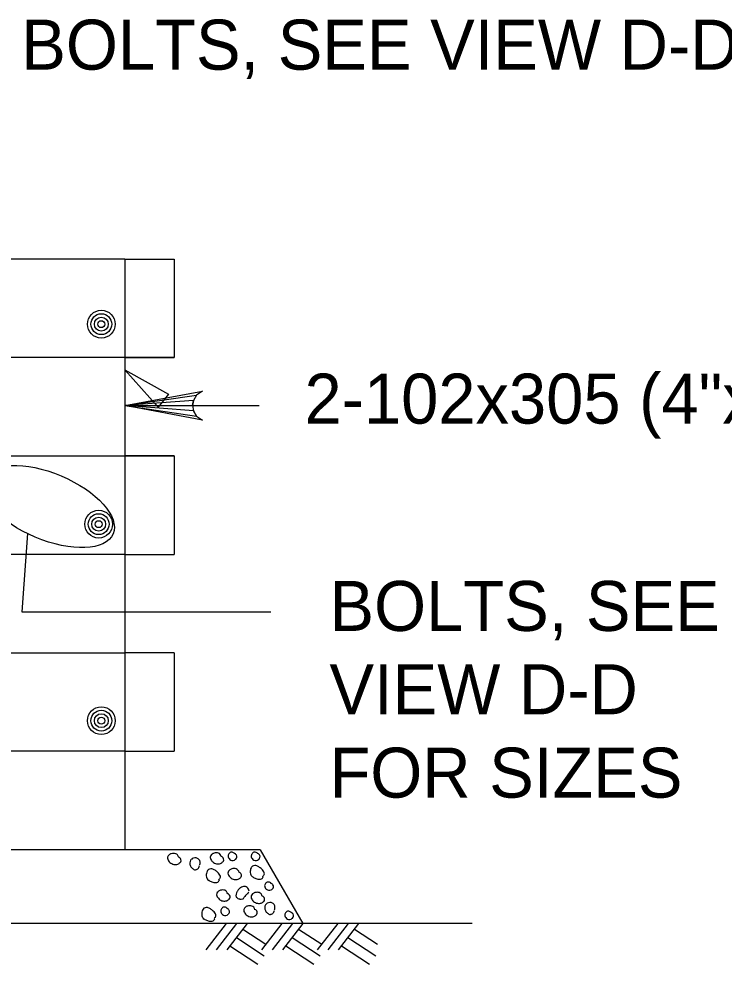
# Model space of a CAD drawing. Extents: x 0 to 36.3, y -44 to 0.
# Drawn here: x 21.652 to 23.344, y -17.273 to -15.005 of the extents above; entities that cross this region are included whole.
import ezdxf

# ---------------------------------------------------------------- set-up
doc = ezdxf.new("R2010")
doc.units = 0
doc.layers.add('3', color=7, linetype='Continuous')
doc.layers.add('5', color=7, linetype='Continuous')

msp = doc.modelspace()

# ---------------------------------------------------------------- linework, layer by layer
at = {"layer": '3'}
for p, q in [((21.9062, -15.5814), (21.5518, -15.5814)), ((21.9062, -15.5814), (21.9062, -16.9987)), ((21.9062, -15.5814), (22.0242, -15.5814)), ((22.0242, -15.5814), (22.0242, -15.8176)), ((21.9062, -15.8176), (21.5518, -15.8176)), ((22.0242, -15.8176), (21.8766, -15.8176)), ((21.9062, -15.8176), (22.0242, -15.8176)), ((21.5518, -16.0538), (21.9062, -16.0538)), ((21.8766, -16.0538), (22.0242, -16.0538)), ((22.0242, -16.0538), (21.9062, -16.0538)), ((22.0242, -16.0538), (22.0242, -16.29)), ((21.9062, -16.29), (21.5518, -16.29)), ((21.9062, -16.29), (22.0242, -16.29)), ((21.5518, -16.5263), (21.9062, -16.5263)), ((22.0242, -16.5263), (21.9062, -16.5263)), ((22.0242, -16.5263), (22.0242, -16.7625)), ((21.9062, -16.7625), (21.5518, -16.7625)), ((21.9062, -16.7625), (22.0242, -16.7625)), ((22.2309, -16.9987), (18.2742, -16.9987)), ((22.2309, -16.9987), (22.3332, -17.1758)), ((22.7392, -17.1758), (17.728, -17.1758)), ((22.149, -17.1758), (22.1002, -17.2395)), ((22.1742, -17.1758), (22.1253, -17.2395)), ((22.1993, -17.1758), (22.1505, -17.2395)), ((22.1891, -17.1892), (22.2446, -17.2257)), ((22.2828, -17.1758), (22.234, -17.2395)), ((22.308, -17.1758), (22.2592, -17.2395)), ((22.3332, -17.1758), (22.2844, -17.2395)), ((22.323, -17.1892), (22.3785, -17.2257)), ((22.4168, -17.1758), (22.3679, -17.2395)), ((22.4419, -17.1758), (22.3931, -17.2395)), ((22.4671, -17.1758), (22.4183, -17.2395)), ((22.4568, -17.1892), (22.5123, -17.2257)), ((22.1737, -17.2093), (22.2407, -17.2532)), ((22.3076, -17.2093), (22.3746, -17.2532)), ((22.4415, -17.2093), (22.5084, -17.2532)), ((22.1583, -17.2293), (22.2253, -17.2733)), ((22.2922, -17.2293), (22.3592, -17.2733)), ((22.4261, -17.2293), (22.4931, -17.2733))]:
    msp.add_line(p, q, dxfattribs=at)
for centre, radius in [((21.8496, -15.7374), 0.0333), ((21.8496, -15.7374), 0.025), ((21.8496, -15.7374), 0.0167), ((21.8496, -15.7374), 0.00833), ((21.8433, -16.2174), 0.0333), ((21.8433, -16.2174), 0.025), ((21.8433, -16.2174), 0.0167), ((21.8433, -16.2174), 0.00833), ((21.8496, -16.6891), 0.0333), ((21.8496, -16.6891), 0.025), ((21.8496, -16.6891), 0.0167), ((21.8496, -16.6891), 0.00833)]:
    msp.add_circle(centre, radius, dxfattribs=at)
for centre, radius, start, end in [((22.0196, -17.0202), 0.0115, 132.2712, 160.92), ((22.0221, -17.0229), 0.0153, 107.4489, 132.2712), ((22.023, -17.0257), 0.0182, 90, 107.449), ((22.023, -17.023), 0.0155, 71.0851, 90), ((22.0248, -17.0176), 0.00984, 39.2919, 71.0851), ((22.0216, -17.0203), 0.014, 12.7289, 39.2919), ((22.1221, -17.0187), 0.0115, 132.2712, 160.92), ((22.1246, -17.0215), 0.0153, 107.4489, 132.2712), ((22.1255, -17.0242), 0.0182, 90, 107.449), ((22.1255, -17.0215), 0.0155, 71.0851, 90), ((22.1273, -17.0162), 0.00984, 39.2919, 71.0851), ((22.1241, -17.0188), 0.014, 12.7289, 39.2919), ((22.1623, -17.0138), 0.00848, 153.4329, 176.3744), ((22.1635, -17.0139), 0.00973, 176.3744, 204.4459), ((22.1651, -17.0152), 0.0116, 133.8613, 153.4329), ((22.1625, -17.0126), 0.00794, 82.8756, 133.8613), ((22.1623, -17.014), 0.00935, 36.1405, 82.8756), ((22.1664, -17.0162), 0.00871, 33.6924, 77.7435), ((22.1674, -17.0155), 0.0075, 345.9971, 33.6924), ((22.2178, -17.0138), 0.00848, 153.4329, 176.3744), ((22.219, -17.0139), 0.00973, 176.3744, 204.4459), ((22.2206, -17.0152), 0.0116, 133.8613, 153.4329), ((22.218, -17.0126), 0.00794, 82.8756, 133.8613), ((22.2179, -17.014), 0.00935, 36.1405, 82.8756), ((22.222, -17.0162), 0.00871, 33.6924, 77.7435), ((22.223, -17.0155), 0.0075, 345.9971, 33.6924), ((22.0157, -17.0188), 0.00738, 160.92, 203.6312), ((22.0289, -17.013), 0.0219, 203.6312, 228.0682), ((22.0279, -17.0141), 0.0203, 228.0682, 257.7363), ((22.027, -17.0183), 0.0161, 257.7363, 291.1829), ((22.0266, -17.0171), 0.0173, 291.1829, 314.9975), ((22.0322, -17.0252), 0.00907, 36.0298, 75.5915), ((22.0337, -17.0243), 0.00724, 314.9975, 352.2416), ((22.0335, -17.0242), 0.00747, 352.2416, 36.0298), ((22.0758, -17.0311), 0.0139, 162.0407, 192.5299), ((22.0786, -17.0305), 0.0167, 192.5299, 220.2507), ((22.0741, -17.0305), 0.0121, 134.9975, 162.0407), ((22.0753, -17.0317), 0.0137, 109.6149, 134.9975), ((22.0745, -17.0295), 0.0114, 75.9649, 109.6149), ((22.074, -17.0316), 0.0135, 45.0971, 75.9649), ((22.0761, -17.0295), 0.0106, 6.7104, 45.0971), ((22.0736, -17.0358), 0.0117, 330.9432, 352.744), ((22.0743, -17.0297), 0.0124, 331.3493, 6.7104), ((22.1181, -17.0173), 0.00738, 160.92, 203.6312), ((22.1314, -17.0115), 0.0219, 203.6312, 228.0682), ((22.1304, -17.0127), 0.0203, 228.0682, 257.7363), ((22.1295, -17.0168), 0.0161, 257.7363, 291.1829), ((22.129, -17.0156), 0.0173, 291.1829, 314.9975), ((22.1346, -17.0237), 0.00907, 36.0298, 75.5915), ((22.1362, -17.0228), 0.00724, 314.9975, 352.2416), ((22.1359, -17.0227), 0.00747, 352.2416, 36.0298), ((22.1657, -17.0129), 0.0121, 204.4459, 229.5269), ((22.1645, -17.0143), 0.0104, 229.5269, 261.8706), ((22.1647, -17.0132), 0.0114, 261.8706, 292.6593), ((22.1653, -17.0146), 0.0099, 292.6593, 318.8116), ((22.1658, -17.0151), 0.00917, 318.8116, 345.9971), ((22.2188, -17.0473), 0.0109, 111.0358, 142.5289), ((22.2212, -17.0129), 0.0121, 204.4459, 229.5269), ((22.2201, -17.0143), 0.0104, 229.5269, 261.8706), ((22.2185, -17.0467), 0.0102, 78.5014, 111.0358), ((22.2202, -17.0132), 0.0114, 261.8706, 292.6593), ((22.2177, -17.0507), 0.0143, 61.7014, 78.5014), ((22.2208, -17.0146), 0.0099, 292.6593, 318.8116), ((22.2213, -17.0151), 0.00917, 318.8116, 345.9971), ((22.0828, -17.0269), 0.0222, 220.2507, 239.7458), ((22.0747, -17.0408), 0.00621, 239.7458, 277.0923), ((22.0742, -17.0368), 0.0102, 277.0923, 293.1968), ((22.0729, -17.0336), 0.0137, 293.1968, 307.0979), ((22.0752, -17.0367), 0.00977, 307.0979, 330.9432), ((22.1214, -17.0592), 0.0199, 161.5635, 177.6608), ((22.1246, -17.0593), 0.0232, 177.6608, 192.9957), ((22.1161, -17.0574), 0.0143, 142.5289, 161.5635), ((22.1134, -17.0553), 0.0109, 111.0358, 142.5289), ((22.1131, -17.0547), 0.0102, 78.5014, 111.0358), ((22.1123, -17.0587), 0.0143, 61.7014, 78.5014), ((22.0957, -17.0895), 0.0493, 52.6686, 61.7014), ((22.1013, -17.0822), 0.0401, 38.6623, 52.6686), ((22.1214, -17.0662), 0.0144, 15.2216, 38.6623), ((22.1608, -17.0551), 0.00738, 160.92, 203.6312), ((22.1647, -17.0565), 0.0115, 132.2712, 160.92), ((22.174, -17.0493), 0.0219, 203.6312, 228.0682), ((22.1672, -17.0593), 0.0153, 107.4489, 132.2712), ((22.1681, -17.062), 0.0182, 90, 107.449), ((22.1681, -17.0593), 0.0155, 71.0851, 90), ((22.1699, -17.054), 0.00984, 39.2919, 71.0851), ((22.1667, -17.0566), 0.014, 12.7289, 39.2919), ((22.1773, -17.0615), 0.00907, 36.0298, 75.5915), ((22.1786, -17.0606), 0.00747, 352.2416, 36.0298), ((22.2268, -17.0511), 0.0199, 161.5635, 177.6608), ((22.23, -17.0513), 0.0232, 177.6608, 192.9957), ((22.2204, -17.0535), 0.0133, 192.9957, 213.2749), ((22.2215, -17.0493), 0.0143, 142.5289, 161.5635), ((22.2011, -17.0815), 0.0493, 52.6686, 61.7014), ((22.2067, -17.0742), 0.0401, 38.6623, 52.6686), ((22.2266, -17.0516), 0.0153, 310.4771, 334.6604), ((22.2268, -17.0581), 0.0144, 15.2216, 38.6623), ((22.2353, -17.0558), 0.00558, 334.6604, 15.2216), ((22.115, -17.0615), 0.0133, 192.9957, 213.2749), ((22.1137, -17.0624), 0.0118, 213.2749, 237.2671), ((22.1274, -17.0411), 0.037, 237.2671, 250.7161), ((22.1257, -17.0459), 0.0319, 250.7161, 266.6338), ((22.1245, -17.0672), 0.0106, 266.6338, 294.3814), ((22.1266, -17.0718), 0.00552, 294.3814, 320.1919), ((22.1201, -17.0664), 0.0139, 320.1919, 336.3613), ((22.1211, -17.0597), 0.0153, 310.4771, 334.6604), ((22.1299, -17.0638), 0.00558, 334.6604, 15.2216), ((22.173, -17.0505), 0.0203, 228.0682, 257.7363), ((22.1721, -17.0546), 0.0161, 257.7363, 291.1829), ((22.1717, -17.0535), 0.0173, 291.1829, 314.9975), ((22.1788, -17.0606), 0.00724, 314.9975, 352.2416), ((22.2191, -17.0543), 0.0118, 213.2749, 237.2671), ((22.2328, -17.0331), 0.037, 237.2671, 250.7161), ((22.2311, -17.0379), 0.0319, 250.7161, 266.6338), ((22.2299, -17.0591), 0.0106, 266.6338, 294.3814), ((22.232, -17.0638), 0.00552, 294.3814, 320.1919), ((22.2255, -17.0584), 0.0139, 320.1919, 336.3613), ((22.25, -17.0854), 0.00848, 153.4329, 176.3744), ((22.2528, -17.0868), 0.0116, 133.8613, 153.4329), ((22.2502, -17.0842), 0.00794, 82.8756, 133.8613), ((22.25, -17.0856), 0.00935, 36.1405, 82.8756), ((22.2541, -17.0878), 0.00871, 33.6924, 77.7435), ((22.1334, -17.1066), 0.00738, 160.92, 203.6312), ((22.1374, -17.108), 0.0115, 132.2712, 160.92), ((22.1399, -17.1108), 0.0153, 107.4489, 132.2712), ((22.1407, -17.1135), 0.0182, 90, 107.449), ((22.1407, -17.1108), 0.0155, 71.0851, 90), ((22.1426, -17.1055), 0.00984, 39.2919, 71.0851), ((22.1394, -17.1081), 0.014, 12.7289, 39.2919), ((22.1499, -17.113), 0.00907, 36.0298, 75.5915), ((22.1914, -17.1092), 0.0187, 159.491, 180), ((22.1984, -17.1117), 0.0261, 144.4599, 159.491), ((22.2003, -17.1131), 0.0285, 130.0785, 144.4599), ((22.1922, -17.1035), 0.0159, 114.4421, 130.0785), ((22.1961, -17.112), 0.0253, 102.0363, 114.4421), ((22.1929, -17.0972), 0.0101, 50.53, 102.0363), ((22.2382, -17.1442), 0.0552, 134.9975, 140.4906), ((22.2511, -17.157), 0.0734, 130.2337, 134.9975), ((22.19, -17.1007), 0.0146, 8.2706, 50.53), ((22.2202, -17.1136), 0.0115, 132.2712, 160.92), ((22.2228, -17.1164), 0.0153, 107.4489, 132.2712), ((22.2236, -17.1191), 0.0182, 90, 107.449), ((22.2236, -17.1164), 0.0155, 71.0851, 90), ((22.2254, -17.1111), 0.00984, 39.2919, 71.0851), ((22.2222, -17.1137), 0.014, 12.7289, 39.2919), ((22.2512, -17.0855), 0.00973, 176.3744, 204.4459), ((22.2534, -17.0845), 0.0121, 204.4459, 229.5269), ((22.2523, -17.0859), 0.0104, 229.5269, 261.8706), ((22.2524, -17.0848), 0.0114, 261.8706, 292.6593), ((22.253, -17.0862), 0.0099, 292.6593, 318.8116), ((22.2535, -17.0867), 0.00917, 318.8116, 345.9971), ((22.2552, -17.0871), 0.0075, 345.9971, 33.6924), ((22.1467, -17.1008), 0.0219, 203.6312, 228.0682), ((22.1457, -17.102), 0.0203, 228.0682, 257.7363), ((22.1448, -17.1061), 0.0161, 257.7363, 291.1829), ((22.1443, -17.1049), 0.0173, 291.1829, 314.9975), ((22.1515, -17.1121), 0.00724, 314.9975, 352.2416), ((22.1512, -17.1121), 0.00747, 352.2416, 36.0298), ((22.1797, -17.1092), 0.00701, 180, 213.8235), ((22.1802, -17.1089), 0.00751, 213.8235, 243.437), ((22.1834, -17.1024), 0.0147, 243.437, 264.4731), ((22.1842, -17.0942), 0.023, 264.4731, 280.304), ((22.1875, -17.1123), 0.00464, 280.304, 316.0526), ((22.1797, -17.1048), 0.0154, 316.0526, 327.4482), ((22.2274, -17.1352), 0.0412, 140.4906, 147.4482), ((22.2163, -17.1123), 0.00738, 160.92, 203.6312), ((22.2296, -17.1065), 0.0219, 203.6312, 228.0682), ((22.2285, -17.1076), 0.0203, 228.0682, 257.7363), ((22.2276, -17.1117), 0.0161, 257.7363, 291.1829), ((22.2272, -17.1106), 0.0173, 291.1829, 314.9975), ((22.2328, -17.1186), 0.00907, 36.0298, 75.5915), ((22.2343, -17.1177), 0.00724, 314.9975, 352.2416), ((22.2341, -17.1177), 0.00747, 352.2416, 36.0298), ((22.255, -17.1388), 0.0137, 109.6149, 134.9975), ((22.2542, -17.1367), 0.0114, 75.9649, 109.6149), ((22.2537, -17.1387), 0.0135, 45.0971, 75.9649), ((22.1104, -17.152), 0.0199, 161.5635, 177.6608), ((22.1051, -17.1502), 0.0143, 142.5289, 161.5635), ((22.1024, -17.1482), 0.0109, 111.0358, 142.5289), ((22.1021, -17.1476), 0.0102, 78.5014, 111.0358), ((22.1013, -17.1516), 0.0143, 61.7014, 78.5014), ((22.0848, -17.1824), 0.0493, 52.6686, 61.7014), ((22.0903, -17.175), 0.0401, 38.6623, 52.6686), ((22.1104, -17.159), 0.0144, 15.2216, 38.6623), ((22.1446, -17.1458), 0.00848, 153.4329, 176.3744), ((22.1458, -17.1459), 0.00973, 176.3744, 204.4459), ((22.1474, -17.1472), 0.0116, 133.8613, 153.4329), ((22.148, -17.1449), 0.0121, 204.4459, 229.5269), ((22.1448, -17.1445), 0.00794, 82.8756, 133.8613), ((22.1446, -17.1459), 0.00935, 36.1405, 82.8756), ((22.1487, -17.1481), 0.00871, 33.6924, 77.7435), ((22.1481, -17.147), 0.00917, 318.8116, 345.9971), ((22.1497, -17.1475), 0.0075, 345.9971, 33.6924), ((22.1986, -17.1444), 0.00738, 160.92, 203.6312), ((22.2025, -17.1458), 0.0115, 132.2712, 160.92), ((22.2119, -17.1386), 0.0219, 203.6312, 228.0682), ((22.2051, -17.1486), 0.0153, 107.4489, 132.2712), ((22.2059, -17.1513), 0.0182, 90, 107.449), ((22.2059, -17.1486), 0.0155, 71.0851, 90), ((22.2077, -17.1433), 0.00984, 39.2919, 71.0851), ((22.2045, -17.1459), 0.014, 12.7289, 39.2919), ((22.2151, -17.1508), 0.00907, 36.0298, 75.5915), ((22.2164, -17.1499), 0.00747, 352.2416, 36.0298), ((22.2555, -17.1383), 0.0139, 162.0407, 192.5299), ((22.2583, -17.1376), 0.0167, 192.5299, 220.2507), ((22.2538, -17.1377), 0.0121, 134.9975, 162.0407), ((22.2625, -17.1341), 0.0222, 220.2507, 239.7458), ((22.2549, -17.1439), 0.00977, 307.0979, 330.9432), ((22.2557, -17.1367), 0.0106, 6.7104, 45.0971), ((22.2533, -17.143), 0.0117, 330.9432, 352.744), ((22.2539, -17.1369), 0.0124, 331.3493, 6.7104), ((22.301, -17.1568), 0.0116, 133.8613, 153.4329), ((22.2985, -17.1542), 0.00794, 82.8756, 133.8613), ((22.2983, -17.1556), 0.00935, 36.1405, 82.8756), ((22.3024, -17.1578), 0.00871, 33.6924, 77.7435), ((22.1136, -17.1521), 0.0232, 177.6608, 192.9957), ((22.104, -17.1544), 0.0133, 192.9957, 213.2749), ((22.1027, -17.1552), 0.0118, 213.2749, 237.2671), ((22.1164, -17.1339), 0.037, 237.2671, 250.7161), ((22.1147, -17.1388), 0.0319, 250.7161, 266.6338), ((22.1135, -17.16), 0.0106, 266.6338, 294.3814), ((22.1156, -17.1647), 0.00552, 294.3814, 320.1919), ((22.1091, -17.1593), 0.0139, 320.1919, 336.3613), ((22.1102, -17.1525), 0.0153, 310.4771, 334.6604), ((22.1189, -17.1567), 0.00558, 334.6604, 15.2216), ((22.1468, -17.1462), 0.0104, 229.5269, 261.8706), ((22.147, -17.1452), 0.0114, 261.8706, 292.6593), ((22.1476, -17.1466), 0.0099, 292.6593, 318.8116), ((22.2108, -17.1398), 0.0203, 228.0682, 257.7363), ((22.2099, -17.1439), 0.0161, 257.7363, 291.1829), ((22.2095, -17.1428), 0.0173, 291.1829, 314.9975), ((22.2166, -17.1499), 0.00724, 314.9975, 352.2416), ((22.2544, -17.1479), 0.00621, 239.7458, 277.0923), ((22.2539, -17.1439), 0.0102, 277.0923, 293.1968), ((22.2526, -17.1408), 0.0137, 293.1968, 307.0979), ((22.2982, -17.1554), 0.00848, 153.4329, 176.3744), ((22.2995, -17.1555), 0.00973, 176.3744, 204.4459), ((22.3017, -17.1545), 0.0121, 204.4459, 229.5269), ((22.3005, -17.1559), 0.0104, 229.5269, 261.8706), ((22.3007, -17.1548), 0.0114, 261.8706, 292.6593), ((22.3013, -17.1562), 0.0099, 292.6593, 318.8116), ((22.3018, -17.1567), 0.00917, 318.8116, 345.9971), ((22.3034, -17.1571), 0.0075, 345.9971, 33.6924)]:
    msp.add_arc(centre, radius, start, end, dxfattribs=at)
at = {"layer": '5'}
msp.add_lwpolyline([(22.0105, -15.9055), (21.9861, -15.9363), (21.9058, -15.8474)], close=True, dxfattribs=at)
for points in [[(21.9062, -15.9329), (22.0926, -15.898), (22.0782, -15.9079), (22.0708, -15.9204), (22.0687, -15.9329), (22.0708, -15.9454), (22.0782, -15.9579), (22.0926, -15.9679), (21.9062, -15.9329), (22.0782, -15.9579), (22.0708, -15.9454), (21.9062, -15.9329), (22.0687, -15.9329), (22.0708, -15.9204), (21.9062, -15.9329), (22.0782, -15.9079)], [(21.9062, -15.9329), (22.2282, -15.9329)], [(21.6722, -16.2401), (21.6587, -16.4275), (22.2562, -16.4275)]]:
    msp.add_lwpolyline(points, dxfattribs=at)
msp.add_ellipse((21.7222, -16.1751), major_axis=(-0.1556, 0.0657), ratio=0.473013, dxfattribs=at)

# ---------------------------------------------------------------- texts
for s, p in [('BOLTS, SEE VIEW D-D FOR SIZES', (21.6576, -15.1265)), ('2-102x305 (4"x12")', (22.3371, -15.9761)), ('BOLTS, SEE', (22.397, -16.4737)), ('VIEW D-D', (22.397, -16.6737)), ('FOR SIZES', (22.397, -16.8738))]:
    msp.add_text(s, height=0.12, dxfattribs=at).set_placement(p)

doc.saveas('drawing.dxf')
